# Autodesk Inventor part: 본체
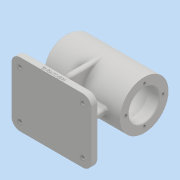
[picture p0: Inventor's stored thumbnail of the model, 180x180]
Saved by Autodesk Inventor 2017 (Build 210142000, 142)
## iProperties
Part Number: 본체
Material: 일반
Document SubType Name: Modeling
Designer: mrc
Density: 1 g/cm^3
Appearance: 기본값
Mass: 380.051 g
Surface Area: 758.291 cm^2
Volume: 380.051 cm^3
Author: mrc
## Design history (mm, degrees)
sketch "스케치2"
  geometry: L1 (0, 21)-(0, 34); L2 (0, 34)-(-112, 34); L3 (-112, 34)-(-112, 0); L4 (-112, 0)-(0, 0); L5 (0, 21)-(-15, 21); L6 (-15, 21)-(-15, 24); L7 (-15, 24)-(-69, 24); L8 (-69, 24)-(-69, 21); L9 (-69, 21)-(-81, 21); L10 (-81, 21)-(-81, 17.5); L11 (-81, 17.5)-(-99, 17.5); L12 (-99, 17.5)-(-99, 16); L13 (-99, 16)-(-103, 16); L14 (-103, 16)-(-103, 10.5); L15 (-103, 10.5)-(-106, 10.5); L16 (-106, 10.5)-(-106, 0); L17 (-81, 16)-(-81, 17.5)
  constraints: 34 end point, 10 perpendicular, 3 point on line, 1 vertical
  dimensions: "d1" = 112 distance of L1.end L2.end; "d3" = 15 distance of L1.start L5.end; "d5" = 54 distance of L6.end L7.end; "d7" = 12 distance of L8.end L9.end; "d9" = 18 distance of L10.end L11.end; "d13" = 4 distance of L12.end L13.end; "d16" = 10.5 distance of L15.end L16.end; "d17" = 16 distance between parallel lines of L4 L13; "d18" = 17.5 distance between parallel lines of L4 L11; "d19" = 21 distance between parallel lines of L4 L9; "d20" = 24 distance between parallel lines of L4 L7
revolve "회전1" sketch "스케치2" stored, may be unused: angle "d21" = 90 deg
fillet "모깎기1" dims "d22" = 0.3
fillet "모깎기2" dims "d23" = 0.3
fillet "모깎기3" dims "d24" = 3
chamfer "모따기1" distance "d25" = 1; stored, may be unused: second distance "d26" = 2, angle "d27" = 45 deg
fillet "모깎기4" dims "d28" = 10
sketch "스케치3" dims "d29" = 52
  geometry: 3 further points
  constraints: 1 coincident, 1 vertical alignment, 2 other
hole "구멍1" sketch "스케치3" at (0, 26) diameter "d30" = 3.459; stored, may be unused: countersink angle "d34" = 90 deg, drill point angle "d36" = 118 deg; dims "d31" = 8, "d32" = 4, "d33" = 2, "d35" = 11
node "작업 평면1"
sketch "스케치4"
  geometry: L1 (100, -45)-(12, -45); L2 (0, -33)-(0, 33); L3 (12, 45)-(100, 45); L4 (112, 33)-(112, -33); L5 (112, -45)-(0, 45); L6 (0, -45)-(112, 45); L7 (0, 34)-(0, -34) reference; A1 r 12 centre (100, -33) between (100, -45) and (112, -33); A2 r 12 centre (100, 33) between (112, 33) and (100, 45); A3 r 12 centre (12, 33) between (12, 45) and (0, 33); A4 r 12 centre (12, -33) between (0, -33) and (12, -45); 2 further points
  constraints: 12 end point, 9 point on line, 8 point on circle, 8 tangent, 4 centre point, 3 equal radius, 2 midpoint, 2 parallel, 1 horizontal, 1 perpendicular
  dimensions: "d41" = 112 distance of L5.end L6.end; "d42" = 90 distance of L6.start L5.end; "d43" = 12 radius of A1
extrude "돌출1" join sketch "스케치4" distance "d44" = 10; taper "d45" = 0 deg
sketch "스케치5"
  geometry: L1 (-94, -4)-(-18, -4); L2 (-18, -4)-(-18, 4); L3 (-18, 4)-(-94, 4); L4 (-94, 4)-(-94, -4); L5 (-94, -4)-(-18, 4); L6 (-18, -4)-(-94, 4); L7 (-112, 33)-(-112, -33) reference; L8 (-60, 34)-(-52, 34); L9 (-52, 34)-(-52, -34); L10 (-52, -34)-(-60, -34); L11 (-60, -34)-(-60, 34); L12 (-60, 34)-(-52, -34); L13 (-52, 34)-(-60, -34); L14 (-100, -45)-(-12, -45) reference; 2 further points
  constraints: 24 end point, 4 midpoint, 4 parallel, 2 horizontal, 2 perpendicular
  dimensions: "d46" = 76 distance of L3.end L2.end; "d47" = 8 distance of L2.end L1.end; "d48" = 56 distance from line of L7 point (-56, 0); "d49" = 8 distance of L9.end L10.end; "d50" = 68 distance of L8.end L9.end; "d51" = 49 distance between parallel lines of L14 L3
extrude "돌출2" join sketch "스케치5" stored distance "d52" = 10; taper "d53" = 0 deg
sketch "스케치6"
  geometry: A1 r 12 centre (-100, 33) between (-100, 45) and (-112, 33) reference; A2 r 12 centre (-12, 33) between (0, 33) and (-12, 45) reference; 3 further points
  constraints: 2 coincident
hole "구멍2" sketch "스케치6" at (-100, 33), (-12, 33) diameter "d54" = 5.5; stored, may be unused: countersink angle "d58" = 90 deg, drill point angle "d60" = 0 deg; dims "d55" = 8, "d56" = 9.5, "d57" = 5.4, "d59" = 10
fillet "모깎기5" dims "d61" = 3
fillet "모깎기6" dims "d62" = 3
fillet "모깎기7" dims "d63" = 3
fillet "모깎기8" dims "d64" = 3
fillet "모깎기9" dims "d65" = 3
fillet "모깎기10" dims "d66" = 3
fillet "모깎기11" dims "d67" = 3
sketch "스케치7"
  geometry: L1 (-12, 0)-(-12, 7) reference; L2 (0, 0)-(88, 0) reference; L3 (100, 0)-(100, 7) reference; 2 further points
  constraints: 1 other
  dimensions: "d69" = 3 distance from line of L2 point (44, 3); "d72" = 56 distance from line of point (44, 3) L3
feature "엠보싱1" sketch "스케치7" dims "d70" = 0.5, "d71" = 0
node "솔리드1"
pattern_circular "원형 패턴1" dims angle "d38" = 360 deg
mirror "미러1"
other parameters: "d10" = 90 deg (derived), "d40" = -74
